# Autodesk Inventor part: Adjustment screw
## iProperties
Created: 2006-10
Part Number: Adjustment screw
Document SubType Name: Modeling
Designer: John Croya
Density: 1 g/cm^3
Control State: 0
Master: False
Checked Out: False
Shininess: 64.0
Angle Display Precision: 2
Document Length Units: 11272
Document Angle Units: 11279
Document Time Units: 11290
Document Mass Units: 11286
Document Length Units Precision: 3
Document Angle Units Precision: 2
Compacted: True
Density: 0.0
Volumn: 0.0
Area: 0.0
PropertySet Name: Model Information
Author: John Croya
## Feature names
1. Revolution1
2. Coil1
3. Extrusion1
